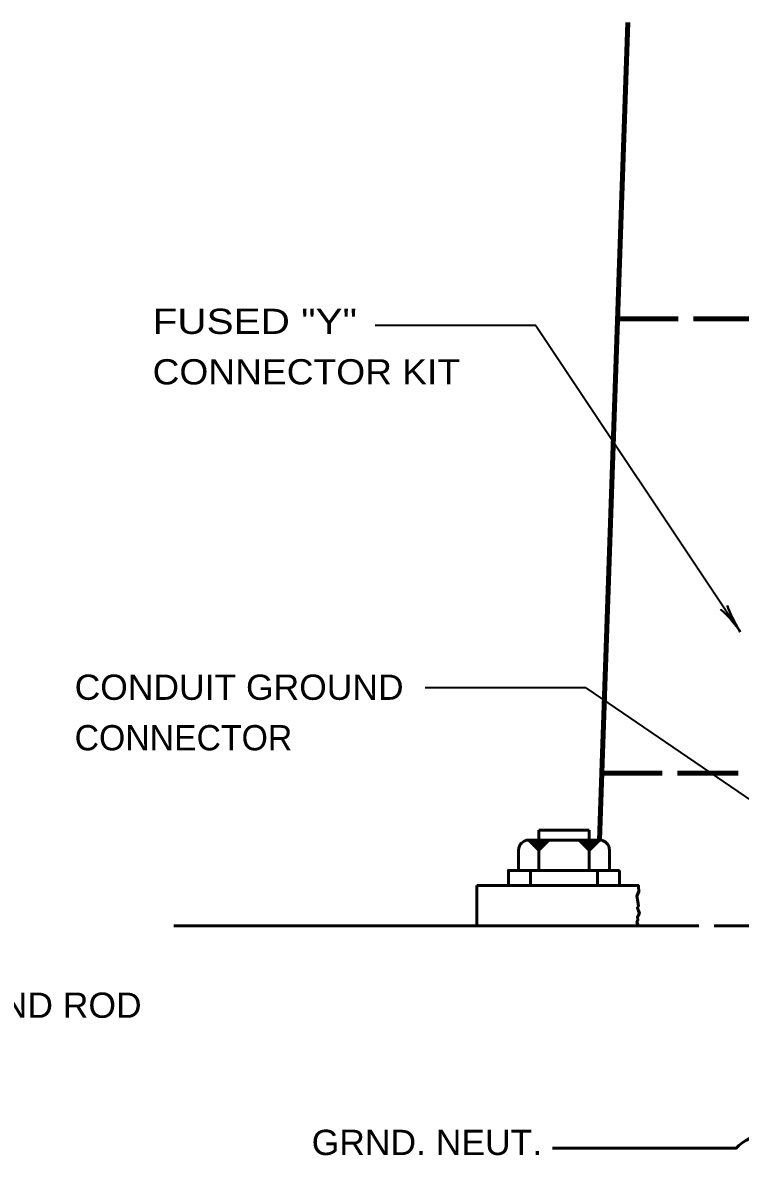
# Model space of a CAD drawing. Extents: x -153 to 527, y -247 to 194.
# Drawn here: x 31.2 to 102.3, y -177.6 to -65.4 of the extents above; entities that cross this region are included whole.
import ezdxf

# ---------------------------------------------------------------- set-up
doc = ezdxf.new("R2010")
doc.units = 0
doc.linetypes.add('LONG_DASHED', pattern=[7.5, 6, -1.5])
doc.layers.add('1', color=7, linetype='Continuous', lineweight=53)

msp = doc.modelspace()

# ---------------------------------------------------------------- linework, layer by layer
at = {"layer": '1', "lineweight": 90}
msp.add_line((88.334, -146.336), (91.16, -65.386), dxfattribs=at)
at = {"layer": '1', "linetype": 'LONG_DASHED', "lineweight": 90}
for p, q in [((90.136, -94.723), (132.839, -94.723)), ((88.564, -139.723), (134.41, -139.723))]:
    msp.add_line(p, q, dxfattribs=at)
at = {"layer": '1', "lineweight": 35}
for p, q in [((82.033, -95.376), (66.124, -95.376)), ((82.033, -95.376), (102.277, -125.704)), ((87.001, -131.25), (71.092, -131.25)), ((87.001, -131.25), (117.556, -152.159))]:
    msp.add_line(p, q, dxfattribs=at)
at = {"layer": '1'}
for p, q in [((82.334, -145.336), (82.334, -149.336)), ((82.334, -145.336), (87.334, -145.336)), ((87.334, -145.336), (87.334, -149.336)), ((81.334, -146.336), (88.334, -146.336)), ((82.334, -147.336), (81.334, -146.336)), ((81.416, -146.419), (81.499, -146.336)), ((81.429, -146.432), (81.512, -146.35)), ((81.446, -146.449), (81.529, -146.367)), ((81.45, -146.452), (81.532, -146.37)), ((81.454, -146.457), (81.537, -146.375)), ((81.456, -146.459), (81.538, -146.376)), ((81.459, -146.462), (81.541, -146.379)), ((81.465, -146.468), (81.596, -146.336)), ((81.468, -146.471), (81.602, -146.336)), ((81.476, -146.478), (81.618, -146.336)), ((81.479, -146.482), (81.624, -146.336)), ((81.489, -146.492), (81.571, -146.409)), ((81.491, -146.494), (81.649, -146.336)), ((81.498, -146.5), (81.662, -146.336)), ((81.5, -146.502), (81.582, -146.42)), ((81.507, -146.51), (81.681, -146.336)), ((81.51, -146.513), (81.593, -146.431)), ((81.514, -146.517), (81.596, -146.434)), ((81.515, -146.518), (81.696, -146.336)), ((81.526, -146.529), (81.718, -146.336)), ((81.529, -146.532), (81.612, -146.45)), ((81.534, -146.537), (81.617, -146.454)), ((81.537, -146.54), (81.74, -146.336)), ((81.541, -146.544), (81.749, -146.336)), ((81.542, -146.545), (81.624, -146.462)), ((81.545, -146.548), (81.628, -146.465)), ((81.549, -146.552), (81.765, -146.336)), ((81.551, -146.554), (81.634, -146.472)), ((81.554, -146.557), (81.775, -146.336)), ((81.554, -146.557), (81.775, -146.336)), ((81.56, -146.563), (81.787, -146.336)), ((81.565, -146.568), (81.797, -146.336)), ((81.574, -146.577), (81.815, -146.336)), ((81.583, -146.586), (81.665, -146.503)), ((81.585, -146.588), (81.837, -146.336)), ((81.594, -146.597), (81.676, -146.514)), ((81.595, -146.598), (81.856, -146.336)), ((81.598, -146.601), (81.862, -146.336)), ((81.6, -146.603), (81.682, -146.52)), ((81.603, -146.606), (81.686, -146.523)), ((81.606, -146.609), (81.689, -146.527)), ((81.611, -146.614), (81.693, -146.531)), ((81.612, -146.615), (81.891, -146.336)), ((81.62, -146.623), (81.703, -146.541)), ((81.623, -146.626), (81.912, -146.336)), ((81.632, -146.635), (81.931, -146.336)), ((81.633, -146.636), (81.715, -146.553)), ((81.64, -146.643), (81.947, -146.336)), ((81.642, -146.645), (81.95, -146.336)), ((81.653, -146.656), (81.972, -146.336)), ((81.655, -146.658), (81.737, -146.575)), ((81.661, -146.663), (81.988, -146.336)), ((81.668, -146.671), (82.003, -146.336)), ((81.675, -146.678), (82.016, -146.336)), ((81.679, -146.682), (82.025, -146.336)), ((81.684, -146.688), (81.767, -146.605)), ((81.69, -146.693), (82.047, -146.336)), ((81.694, -146.697), (81.776, -146.614)), ((81.695, -146.698), (82.057, -146.336)), ((81.7, -146.703), (82.066, -146.336)), ((81.714, -146.717), (82.094, -146.336)), ((81.717, -146.72), (82.1, -146.336)), ((81.717, -146.72), (81.8, -146.638)), ((81.72, -146.723), (82.107, -146.336)), ((81.727, -146.73), (81.809, -146.647)), ((81.728, -146.731), (82.123, -146.336)), ((81.739, -146.742), (82.144, -146.336)), ((81.739, -146.743), (81.822, -146.66)), ((81.744, -146.747), (82.154, -146.336)), ((81.747, -146.75), (81.83, -146.668)), ((81.75, -146.753), (82.166, -146.336)), ((81.755, -146.757), (82.176, -146.336)), ((81.761, -146.764), (82.188, -146.336)), ((81.764, -146.767), (82.195, -146.336)), ((81.769, -146.772), (81.852, -146.69)), ((81.77, -146.773), (82.207, -146.336)), ((81.774, -146.777), (81.856, -146.694)), ((81.783, -146.786), (82.232, -146.336)), ((81.789, -146.793), (81.872, -146.71)), ((81.789, -146.793), (81.872, -146.71)), ((81.792, -146.795), (82.251, -146.336)), ((81.795, -146.798), (82.257, -146.336)), ((81.807, -146.81), (81.889, -146.727)), ((81.81, -146.812), (82.286, -146.336)), ((81.81, -146.812), (82.286, -146.336)), ((81.813, -146.815), (82.292, -146.336)), ((81.816, -146.819), (82.298, -146.336)), ((81.819, -146.822), (82.304, -146.336)), ((81.822, -146.826), (81.905, -146.743)), ((81.825, -146.828), (82.317, -146.336)), ((81.83, -146.833), (82.326, -146.336)), ((81.83, -146.833), (82.326, -146.336)), ((81.838, -146.841), (82.342, -146.336)), ((81.839, -146.843), (81.922, -146.76)), ((81.847, -146.85), (82.361, -146.336)), ((81.847, -146.85), (81.93, -146.768)), ((81.852, -146.855), (82.37, -146.336)), ((81.857, -146.859), (82.38, -146.336)), ((81.86, -146.862), (82.386, -146.336)), ((81.86, -146.863), (81.942, -146.781)), ((81.861, -146.864), (82.389, -146.336)), ((81.864, -146.867), (82.395, -146.336)), ((81.875, -146.878), (82.417, -146.336)), ((81.888, -146.891), (82.442, -146.336)), ((81.888, -146.891), (81.971, -146.809)), ((81.891, -146.894), (81.974, -146.812)), ((81.896, -146.899), (82.458, -146.336)), ((81.902, -146.905), (82.471, -146.336)), ((81.912, -146.915), (81.994, -146.832)), ((81.913, -146.916), (82.492, -146.336)), ((81.918, -146.92), (82.502, -146.336)), ((81.918, -146.921), (82.502, -146.336)), ((81.921, -146.924), (82.508, -146.336)), ((81.921, -146.924), (82.508, -146.336)), ((81.924, -146.927), (82.007, -146.845)), ((81.927, -146.93), (82.521, -146.336)), ((81.933, -146.936), (82.533, -146.336)), ((81.938, -146.941), (82.021, -146.859)), ((81.941, -146.944), (82.549, -146.336)), ((81.947, -146.951), (82.03, -146.868)), ((81.954, -146.957), (82.574, -146.336)), ((81.957, -146.96), (82.04, -146.878)), ((81.96, -146.963), (82.587, -146.336)), ((81.966, -146.969), (82.599, -146.336)), ((81.968, -146.971), (82.602, -146.336)), ((81.974, -146.977), (82.615, -146.336)), ((81.983, -146.986), (82.633, -146.336)), ((81.984, -146.987), (82.066, -146.905)), ((81.993, -146.996), (82.652, -146.336)), ((82.001, -147.004), (82.668, -146.336)), ((82.005, -147.008), (82.677, -146.336)), ((82.01, -147.013), (82.687, -146.336)), ((82.01, -147.014), (82.093, -146.931)), ((82.013, -147.016), (82.693, -146.336)), ((82.024, -147.027), (82.715, -146.336)), ((82.029, -147.032), (82.724, -146.336)), ((82.031, -147.034), (82.672, -146.393)), ((82.032, -147.035), (82.731, -146.336)), ((82.04, -147.043), (82.746, -146.336)), ((82.043, -147.046), (82.752, -146.336)), ((82.043, -147.046), (82.753, -146.336)), ((82.046, -147.049), (82.759, -146.336)), ((82.056, -147.058), (82.778, -146.336)), ((82.07, -147.073), (82.806, -146.336)), ((82.075, -147.077), (82.816, -146.336)), ((82.085, -147.088), (82.837, -146.336)), ((82.092, -147.094), (82.85, -146.336)), ((82.101, -147.104), (82.869, -146.336)), ((82.106, -147.108), (82.878, -146.336)), ((82.111, -147.113), (82.888, -146.336)), ((82.115, -147.118), (82.897, -146.336)), ((82.121, -147.124), (82.909, -146.336)), ((82.129, -147.132), (82.925, -146.336)), ((82.14, -147.143), (82.947, -146.336)), ((82.143, -147.146), (82.953, -146.336)), ((82.156, -147.159), (82.978, -146.336)), ((82.165, -147.168), (82.997, -146.336)), ((82.17, -147.173), (83.007, -146.336)), ((82.173, -147.176), (83.013, -146.336)), ((82.186, -147.189), (83.038, -146.336)), ((82.195, -147.198), (83.057, -146.336)), ((82.2, -147.203), (83.066, -146.336)), ((82.206, -147.209), (83.078, -146.336)), ((82.209, -147.212), (83.085, -146.336)), ((82.212, -147.215), (83.091, -146.336)), ((82.222, -147.225), (83.11, -146.336)), ((82.223, -147.226), (83.113, -146.336)), ((82.231, -147.234), (83.128, -146.336)), ((82.231, -147.234), (83.129, -146.336)), ((82.242, -147.245), (83.151, -146.336)), ((82.247, -147.25), (83.16, -146.336)), ((82.258, -147.261), (83.182, -146.336)), ((82.259, -147.262), (83.185, -146.336)), ((82.275, -147.278), (83.217, -146.336)), ((82.281, -147.284), (83.229, -146.336)), ((82.294, -147.297), (83.254, -146.336)), ((82.306, -147.309), (83.279, -146.336)), ((82.306, -147.309), (83.279, -146.336)), ((82.319, -147.322), (83.304, -146.336)), ((82.334, -147.336), (83.334, -146.336)), ((87.334, -147.336), (86.334, -146.336)), ((87.34, -147.34), (86.34, -146.34)), ((86.352, -146.351), (86.368, -146.336)), ((86.367, -146.366), (86.396, -146.336)), ((86.379, -146.378), (86.421, -146.336)), ((86.385, -146.385), (86.433, -146.336)), ((86.395, -146.394), (86.452, -146.336)), ((86.406, -146.405), (86.474, -146.336)), ((86.415, -146.414), (86.493, -146.336)), ((86.42, -146.419), (86.502, -146.337)), ((86.423, -146.422), (86.505, -146.34)), ((86.435, -146.435), (86.534, -146.336)), ((86.443, -146.442), (86.526, -146.36)), ((86.446, -146.446), (86.529, -146.363)), ((86.453, -146.452), (86.568, -146.336)), ((86.456, -146.455), (86.575, -146.336)), ((86.456, -146.456), (86.539, -146.373)), ((86.461, -146.46), (86.544, -146.378)), ((86.472, -146.471), (86.606, -146.336)), ((86.478, -146.477), (86.618, -146.336)), ((86.483, -146.482), (86.565, -146.399)), ((86.486, -146.485), (86.634, -146.336)), ((86.492, -146.491), (86.647, -146.336)), ((86.495, -146.495), (86.578, -146.412)), ((86.498, -146.497), (86.656, -146.34)), ((86.504, -146.504), (86.672, -146.336)), ((86.506, -146.506), (86.589, -146.423)), ((86.515, -146.515), (86.694, -146.336)), ((86.526, -146.526), (86.716, -146.336)), ((86.528, -146.527), (86.719, -146.336)), ((86.531, -146.53), (86.725, -146.336)), ((86.533, -146.532), (86.728, -146.336)), ((86.536, -146.535), (86.734, -146.336)), ((86.541, -146.54), (86.745, -146.336)), ((86.548, -146.547), (86.756, -146.34)), ((86.561, -146.56), (86.781, -146.34)), ((86.581, -146.58), (86.822, -146.34)), ((86.586, -146.585), (86.835, -146.336)), ((86.592, -146.591), (86.844, -146.34)), ((86.597, -146.596), (86.857, -146.336)), ((86.599, -146.598), (86.86, -146.336)), ((86.605, -146.604), (86.872, -146.336)), ((86.608, -146.607), (86.879, -146.336)), ((86.618, -146.617), (86.7, -146.535)), ((86.619, -146.618), (86.901, -146.336)), ((86.619, -146.618), (86.897, -146.34)), ((86.624, -146.623), (86.91, -146.336)), ((86.63, -146.629), (86.922, -146.336)), ((86.633, -146.632), (86.929, -146.336)), ((86.644, -146.643), (86.951, -146.336)), ((86.649, -146.648), (86.96, -146.336)), ((86.65, -146.649), (86.963, -146.336)), ((86.66, -146.659), (86.982, -146.336)), ((86.663, -146.662), (86.989, -146.336)), ((86.668, -146.667), (86.998, -146.336)), ((86.668, -146.667), (86.957, -146.377)), ((86.682, -146.681), (87.026, -146.336)), ((86.689, -146.689), (87.042, -146.336)), ((86.691, -146.691), (86.774, -146.608)), ((86.693, -146.692), (87.048, -146.336)), ((86.699, -146.698), (87.06, -146.336)), ((86.702, -146.701), (87.064, -146.34)), ((86.705, -146.704), (87.073, -146.336)), ((86.707, -146.706), (87.073, -146.34)), ((86.707, -146.706), (86.996, -146.416)), ((86.724, -146.723), (87.107, -146.34)), ((86.733, -146.733), (87.13, -146.336)), ((86.74, -146.739), (87.142, -146.336)), ((86.748, -146.747), (87.158, -146.336)), ((86.751, -146.75), (87.161, -146.34)), ((86.754, -146.753), (86.837, -146.671)), ((86.761, -146.761), (87.182, -146.34)), ((86.762, -146.761), (87.186, -146.336)), ((86.772, -146.772), (87.208, -146.336)), ((86.777, -146.776), (87.214, -146.34)), ((86.784, -146.783), (87.23, -146.336)), ((86.79, -146.789), (87.239, -146.34)), ((86.796, -146.795), (87.255, -146.336)), ((86.796, -146.796), (86.879, -146.713)), ((86.804, -146.803), (87.27, -146.336)), ((86.81, -146.809), (87.283, -146.336)), ((86.813, -146.812), (87.29, -146.336)), ((86.813, -146.813), (86.896, -146.731)), ((86.816, -146.816), (87.296, -146.337)), ((86.819, -146.819), (87.299, -146.34)), ((86.824, -146.823), (87.303, -146.344)), ((86.826, -146.825), (87.314, -146.336)), ((86.837, -146.836), (87.333, -146.34)), ((86.837, -146.836), (87.333, -146.34)), ((86.84, -146.839), (87.343, -146.336)), ((86.845, -146.844), (87.352, -146.336)), ((86.849, -146.849), (87.361, -146.336)), ((86.862, -146.861), (87.387, -146.336)), ((86.863, -146.863), (87.39, -146.336)), ((86.867, -146.866), (86.949, -146.784)), ((86.873, -146.872), (87.409, -146.336)), ((86.882, -146.881), (87.424, -146.34)), ((86.889, -146.888), (87.44, -146.336)), ((86.898, -146.897), (87.459, -146.336)), ((86.903, -146.902), (87.468, -146.336)), ((86.909, -146.908), (87.477, -146.34)), ((86.91, -146.91), (87.484, -146.336)), ((86.917, -146.916), (87.496, -146.336)), ((86.924, -146.924), (87.508, -146.34)), ((86.925, -146.924), (87.512, -146.336)), ((86.926, -146.925), (87.515, -146.336)), ((86.931, -146.931), (87.013, -146.848)), ((86.934, -146.933), (87.531, -146.336)), ((86.939, -146.938), (87.54, -146.336)), ((86.94, -146.939), (87.54, -146.34)), ((86.945, -146.944), (87.553, -146.336)), ((86.945, -146.944), (87.553, -146.337)), ((86.948, -146.947), (87.556, -146.34)), ((86.95, -146.949), (87.562, -146.336)), ((86.951, -146.951), (87.565, -146.336)), ((86.959, -146.958), (87.581, -146.336)), ((86.975, -146.974), (87.609, -146.34)), ((86.981, -146.98), (87.622, -146.34)), ((86.983, -146.982), (87.628, -146.336)), ((86.989, -146.988), (87.639, -146.338)), ((86.99, -146.989), (87.64, -146.34)), ((86.99, -146.99), (87.073, -146.908)), ((87.001, -147.001), (87.651, -146.351)), ((87.011, -147.01), (87.661, -146.36)), ((87.012, -147.011), (87.684, -146.34)), ((87.033, -147.032), (87.683, -146.382)), ((87.039, -147.038), (87.737, -146.34)), ((87.045, -147.045), (87.754, -146.336)), ((87.05, -147.049), (87.759, -146.34)), ((87.05, -147.049), (87.7, -146.399)), ((87.058, -147.057), (87.779, -146.336)), ((87.062, -147.062), (87.785, -146.34)), ((87.067, -147.066), (87.717, -146.417)), ((87.069, -147.068), (87.801, -146.336)), ((87.074, -147.073), (87.81, -146.336)), ((87.075, -147.074), (87.725, -146.424)), ((87.084, -147.084), (87.832, -146.336)), ((87.097, -147.096), (87.857, -146.336)), ((87.099, -147.098), (87.857, -146.34)), ((87.102, -147.101), (87.752, -146.451)), ((87.106, -147.106), (87.879, -146.334)), ((87.108, -147.107), (87.875, -146.34)), ((87.111, -147.11), (87.885, -146.336)), ((87.112, -147.112), (87.885, -146.34)), ((87.116, -147.115), (87.894, -146.336)), ((87.127, -147.126), (87.916, -146.336)), ((87.136, -147.135), (87.932, -146.34)), ((87.146, -147.145), (87.954, -146.336)), ((87.147, -147.146), (87.954, -146.34)), ((87.15, -147.149), (87.96, -146.34)), ((87.152, -147.151), (87.967, -146.336)), ((87.163, -147.162), (87.985, -146.34)), ((87.165, -147.164), (87.992, -146.336)), ((87.172, -147.171), (88.004, -146.34)), ((87.177, -147.176), (88.013, -146.34)), ((87.18, -147.179), (88.02, -146.34)), ((87.182, -147.181), (88.026, -146.336)), ((87.193, -147.192), (88.045, -146.34)), ((87.202, -147.201), (88.064, -146.34)), ((87.205, -147.204), (88.073, -146.336)), ((87.213, -147.212), (88.085, -146.34)), ((87.215, -147.214), (88.087, -146.341)), ((87.218, -147.217), (88.09, -146.345)), ((87.227, -147.226), (88.1, -146.354)), ((87.229, -147.228), (88.117, -146.34)), ((87.23, -147.229), (88.12, -146.34)), ((87.238, -147.237), (88.135, -146.34)), ((87.248, -147.247), (88.12, -146.374)), ((87.249, -147.248), (88.158, -146.34)), ((87.252, -147.251), (88.125, -146.379)), ((87.254, -147.253), (88.167, -146.34)), ((87.257, -147.256), (88.129, -146.384)), ((87.265, -147.264), (88.189, -146.34)), ((87.265, -147.264), (88.137, -146.392)), ((87.265, -147.264), (88.137, -146.392)), ((87.266, -147.265), (88.192, -146.34)), ((87.266, -147.266), (88.139, -146.393)), ((87.268, -147.267), (88.199, -146.336)), ((87.271, -147.27), (88.144, -146.398)), ((87.279, -147.278), (88.221, -146.336)), ((87.282, -147.281), (88.223, -146.34)), ((87.287, -147.286), (88.159, -146.414)), ((87.288, -147.287), (88.236, -146.34)), ((87.301, -147.3), (88.261, -146.34)), ((87.313, -147.312), (88.289, -146.336)), ((87.313, -147.312), (88.286, -146.34)), ((87.326, -147.325), (88.311, -146.34)), ((87.334, -147.336), (88.334, -146.336)), ((87.34, -147.34), (88.34, -146.34)), ((80.334, -147.336), (80.334, -149.336)), ((82.018, -147.021), (82.101, -146.939)), ((82.043, -147.047), (82.126, -146.964)), ((82.07, -147.073), (82.152, -146.991)), ((82.17, -147.174), (82.253, -147.091)), ((82.206, -147.21), (82.289, -147.127)), ((82.292, -147.296), (82.375, -147.213)), ((87.05, -147.05), (87.132, -146.967)), ((87.077, -147.076), (87.159, -146.994)), ((87.106, -147.106), (87.189, -147.024)), ((87.144, -147.144), (87.227, -147.061)), ((87.177, -147.177), (87.259, -147.094)), ((87.213, -147.213), (87.296, -147.13)), ((87.227, -147.227), (87.31, -147.144)), ((87.291, -147.291), (87.374, -147.209)), ((89.334, -147.336), (89.334, -149.336)), ((81.525, -150.836), (81.525, -149.336)), ((88.136, -150.836), (88.136, -149.336)), ((90.334, -150.836), (90.334, -149.336)), ((76.192, -150.836), (76.192, -154.836)), ((76.192, -150.836), (78.971, -150.836)), ((92.032, -150.836), (78.971, -150.836)), ((92.192, -154.836), (46.192, -154.836)), ((101.879, -176.836), (83.692, -176.836))]:
    msp.add_line(p, q, dxfattribs=at)
at = {"layer": '1', "linetype": 'LONG_DASHED'}
msp.add_line((92.192, -154.836), (129.692, -154.836), dxfattribs=at)
at = {"layer": '1'}
for points in [[(79.334, -150.836), (79.334, -149.336), (90.334, -149.336)], [(78.971, -150.836), (92.192, -150.836), (92.202, -150.938)], [(92.202, -150.938), (92.248, -151.423), (92.047, -151.874), (92.147, -152.426), (92.197, -152.877), (92.097, -153.028), (92.197, -153.329), (92.298, -153.579), (92.097, -153.981), (92.147, -154.231), (92.047, -154.482), (92.192, -154.836)]]:
    msp.add_lwpolyline(points, dxfattribs=at)
for centre, radius, start, end in [((81.334, -147.336), 1, 90, 180), ((88.334, -147.336), 1, 0, 90), ((104.886, -179.736), 4.193, 44.31179, 136.66815)]:
    msp.add_arc(centre, radius, start, end, dxfattribs=at)
at = {"layer": '1', "lineweight": 40}
for centre, major_axis, ratio, start_param, end_param in [((101.831, -124.655), (-0.829, 1.558), 0.07063, 6.2823074, 8.5597026), ((101.442, -124.95), (1.121, -1.399), 0.122415, 0.8963533, 3.1415927)]:
    msp.add_ellipse(centre, major_axis=major_axis, ratio=ratio, start_param=start_param, end_param=end_param, dxfattribs=at)

# ---------------------------------------------------------------- texts
at = {"layer": '1'}
for s, width, p in [('FUSED "Y"', 1.2, (44.099, -96.212)), ('CONNECTOR KIT', 1.1, (44.099, -101.212)), ('CONDUIT GROUND', 1.05, (36.383, -132.445)), ('GROUND ROD', 1.05, (18.636, -163.934)), ('GRND. NEUT.', 1.05, (59.85, -177.517))]:
    msp.add_text(s, height=2.5, dxfattribs=dict(at, width=width)).set_placement(p)
msp.add_text('CONNECTOR', height=2.5, dxfattribs=at).set_placement((36.383, -137.445))

doc.saveas('drawing.dxf')
